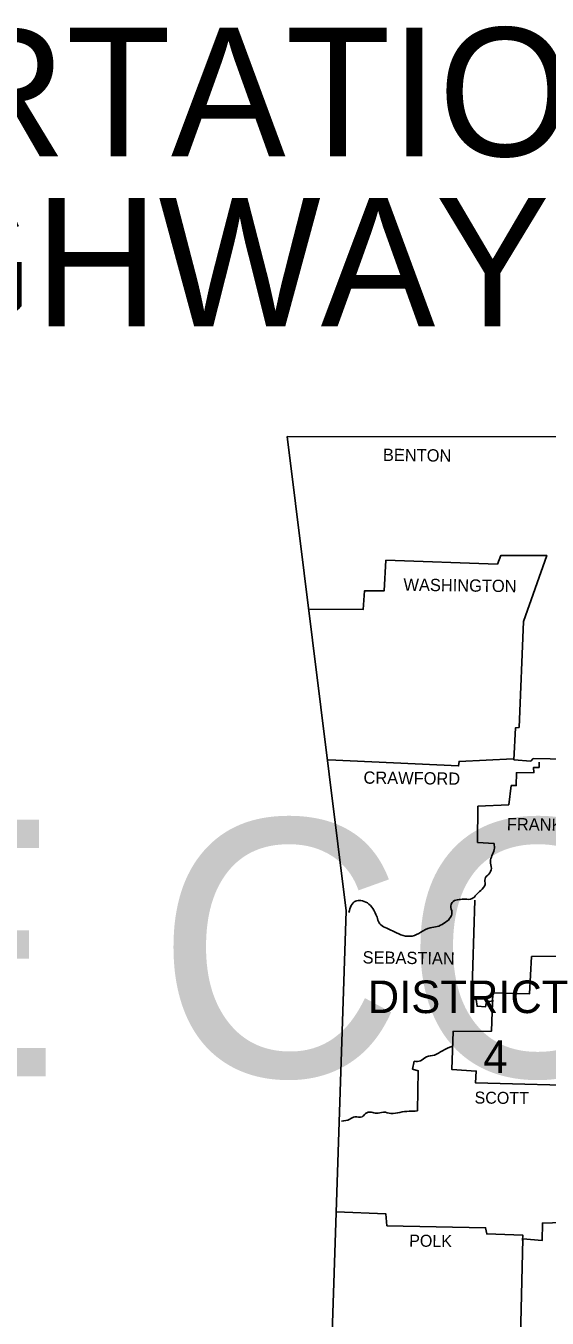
# Model space of a CAD drawing. Extents: x 1373862 to 1376999, y 1168398 to 1170455.
# Drawn here: x 1376071.2 to 1376253.7, y 1169972.5 to 1170425.3 of the extents above; entities that cross this region are included whole.
import ezdxf

# ---------------------------------------------------------------- set-up
doc = ezdxf.new("R2010")
doc.units = 0
doc.layers.add('R_Draft', color=7, linetype='Continuous')

msp = doc.modelspace()

# ---------------------------------------------------------------- linework, layer by layer
at = {"layer": 'R_Draft'}
for points in [[(1376162.7, 1170281.4), (1376324.4, 1170281.3), (1376466.3, 1170281.6), (1376633.7, 1170284.2), (1376711.3, 1170286)], [(1376174.4, 1169843.9), (1376183.4, 1170115.2), (1376162.7, 1170281.4)], [(1376297.1, 1170162.4), (1376296.6, 1170167.7), (1376248.9, 1170168.6), (1376248, 1170167.7), (1376242.1, 1170168.2), (1376242.7, 1170179.4), (1376243.9, 1170179.5), (1376245.5, 1170216.6), (1376253.6, 1170239.8), (1376237.5, 1170239.7), (1376236.3, 1170236.7), (1376197.3, 1170238.1), (1376196.7, 1170227.4), (1376189.8, 1170227.4), (1376189.3, 1170220.8), (1376170.6, 1170220.9)], [(1376177.2, 1170168.1), (1376222.7, 1170166), (1376222.9, 1170167.6), (1376241.9, 1170168.5)], [(1376250.9, 1170167.3), (1376250.9, 1170165.5), (1376249, 1170165.5), (1376249.1, 1170163.7), (1376243, 1170163.6), (1376242.9, 1170159.1), (1376241.2, 1170159.1), (1376240.3, 1170152.4), (1376229.5, 1170151.9), (1376229.4, 1170139.2), (1376235.2, 1170138.8)], [(1376228.4, 1170119), (1376227.4, 1170084.6), (1376228.9, 1170084.2), (1376229.2, 1170081.8), (1376232.2, 1170081.6), (1376232.5, 1170083.3), (1376234.9, 1170083.7)], [(1376262, 1170113.6), (1376261.3, 1170099.3), (1376248.3, 1170099.2), (1376247.6, 1170086.2), (1376234.7, 1170086.5), (1376234.3, 1170073.1), (1376220.8, 1170073), (1376220.4, 1170059.6), (1376228.9, 1170059.1), (1376228.6, 1170055), (1376272, 1170053.8)], [(1376244.1, 1169951.1), (1376245.2, 1170000.3), (1376252, 1169999.7), (1376252.1, 1170005.8), (1376259.1, 1170006), (1376259, 1170007.6), (1376263.7, 1170007.6), (1376263.8, 1170009.8), (1376268.6, 1170009.7), (1376268.2, 1170012.7), (1376273.2, 1170012.8), (1376273.4, 1170071.3), (1376279.4, 1170071.5), (1376279.9, 1170073.1), (1376294.4, 1170072.7), (1376294.3, 1170074.8), (1376297.2, 1170075.1), (1376297.3, 1170077.4), (1376299.8, 1170077.2), (1376301.5, 1170081.2), (1376304.5, 1170083.8), (1376327.3, 1170083.9), (1376327.7, 1170098.3)], [(1376208.3, 1170045.1), (1376208.6, 1170059.2), (1376206.6, 1170059.8), (1376207.2, 1170062.5)], [(1376179.9, 1170009.7), (1376197.2, 1170009.1), (1376197.6, 1170004.9), (1376232.2, 1170004.2), (1376232.6, 1170002), (1376245.2, 1170001.6), (1376245.1, 1169999.7)]]:
    msp.add_lwpolyline(points, dxfattribs=at)
for points in [[(1376235.2, 1170138.8), (1376235.2, 1170136.7), (1376234.4, 1170134.5), (1376233.9, 1170132.6), (1376234.2, 1170130.1), (1376233.3, 1170128.1), (1376232, 1170126.5), (1376232, 1170124.5), (1376230.5, 1170122.4), (1376228.9, 1170120.8), (1376227.5, 1170119.5), (1376225, 1170119.3), (1376222.9, 1170119.2), (1376220.8, 1170118.5), (1376220, 1170117), (1376220.4, 1170114.7), (1376219.6, 1170112.5), (1376217.5, 1170110.8), (1376215.2, 1170109.7), (1376212.8, 1170109.3), (1376209.5, 1170107.7), (1376206.5, 1170106.4), (1376203.3, 1170106.6), (1376200.3, 1170107.9), (1376197.6, 1170109.1), (1376195.5, 1170110.3), (1376193.8, 1170114), (1376192.7, 1170116), (1376190.8, 1170118), (1376188.5, 1170118.8), (1376186.6, 1170118.6), (1376184.3, 1170114.7)], [(1376207.2, 1170062.5), (1376209.4, 1170062.7), (1376211.5, 1170064.1), (1376214.3, 1170064.7), (1376217.1, 1170066.2), (1376220.6, 1170067.8)], [(1376208.3, 1170045.1), (1376205.4, 1170045), (1376202.1, 1170044.6), (1376199.1, 1170044.2), (1376196.4, 1170044.7), (1376193.9, 1170044.3), (1376192.2, 1170044.7), (1376190.1, 1170044.2), (1376188.9, 1170043), (1376186.4, 1170043), (1376184.6, 1170042.2), (1376181.7, 1170041.5)]]:
    msp.add_spline(points, degree=3, dxfattribs=at)

# ---------------------------------------------------------------- texts
for s, height, p in [('ARKANSAS DEPARTMENT OF TRANSPORTATION ', 45, (1374874.9, 1170379.67)), ('CONSTRUCTION PLANS FOR STATE HIGHWAY', 45, (1374897.32, 1170320.07)), ('STRS. & APPRS. (POPE CO.) (S)', 90, (1374732.37, 1170057.19)), ('DISTRICT', 11.4, (1376190.9, 1170079.4)), ('4', 11.4, (1376231.4, 1170058.4))]:
    msp.add_text(s, height=height, dxfattribs=at).set_placement(p)
for s, height, rotation, p in [('BENTON', 4.301, 359.2527, (1376196.2, 1170272.9)), ('WASHINGTON', 4.3, 359.232, (1376203.4, 1170227.4)), ('CRAWFORD', 4.3, 359.2771, (1376189.4, 1170159.8)), ('FRANKLIN', 4.301, 359.1815, (1376239.6, 1170143.5)), ('SEBASTIAN', 4.3, 359.2816, (1376189.1, 1170096.8)), ('SCOTT', 4.201, 359.4063, (1376228.3, 1170047.7)), ('POLK', 4.199, 359.2152, (1376205.4, 1169997.6))]:
    msp.add_text(s, height=height, rotation=rotation, dxfattribs=at).set_placement(p)

doc.saveas('drawing.dxf')
